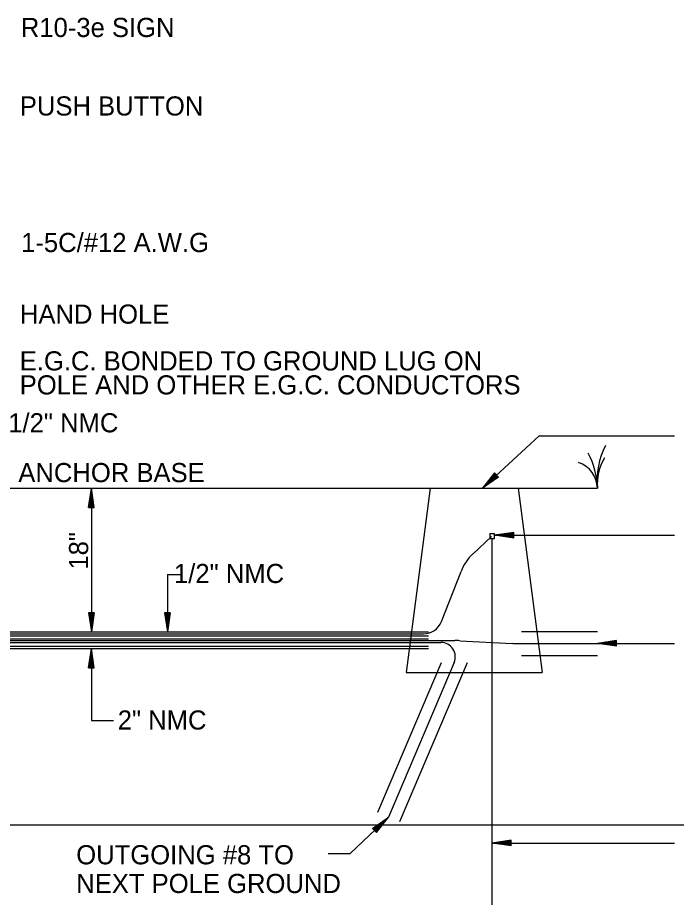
# Model space of a CAD drawing. Extents: x 418532 to 420296, y -565948 to -565286.
# Drawn here: x 418998.3 to 419153.1, y -565528 to -565321.2 of the extents above; entities that cross this region are included whole.
import ezdxf

# ---------------------------------------------------------------- set-up
doc = ezdxf.new("R2010")
doc.units = 0
doc.layers.add('R_Draft', color=7, linetype='Continuous')
doc.layers.add('Template', color=7, linetype='Continuous')

msp = doc.modelspace()

# ---------------------------------------------------------------- linework, layer by layer
at = {"layer": 'R_Draft'}
for p, q in [((419107.56, -565431.83), (419120.8, -565419.49)), ((419120.8, -565419.49), (419152.64, -565419.49)), ((419110.35, -565428.23), (419107.56, -565431.83)), ((419110.43, -565428.31), (419108.1, -565431.31)), ((419110.51, -565428.4), (419108.66, -565430.77)), ((419110.59, -565428.48), (419109.21, -565430.26)), ((419111.05, -565428.96), (419109.21, -565430.26)), ((419110.67, -565428.56), (419109.76, -565429.73)), ((419110.97, -565428.88), (419109.76, -565429.73)), ((419110.74, -565428.65), (419110.3, -565429.21)), ((419110.89, -565428.8), (419110.3, -565429.21)), ((419111.28, -565429.21), (419110.35, -565428.23)), ((419111.28, -565429.21), (419107.56, -565431.83)), ((419111.21, -565429.13), (419108.1, -565431.31)), ((419111.13, -565429.05), (419108.66, -565430.77)), ((418896.71, -565431.83), (419134.51, -565431.83)), ((419014.94, -565436.33), (419015.61, -565431.83)), ((419015.05, -565436.33), (419015.61, -565432.58)), ((419015.61, -565431.83), (419015.61, -565465.58)), ((419016.29, -565436.33), (419015.61, -565431.83)), ((419016.18, -565436.33), (419015.61, -565432.58)), ((419095.21, -565431.83), (419089.58, -565475.16)), ((419115.91, -565431.83), (419121.53, -565475.16)), ((419015.17, -565436.33), (419015.61, -565433.35)), ((419015.28, -565436.33), (419015.61, -565434.1)), ((419015.4, -565436.33), (419015.61, -565434.86)), ((419016.06, -565436.33), (419015.61, -565433.35)), ((419015.95, -565436.33), (419015.61, -565434.1)), ((419015.83, -565436.33), (419015.61, -565434.86)), ((419014.94, -565436.33), (419016.29, -565436.33)), ((419015.51, -565436.33), (419015.61, -565435.62)), ((419015.72, -565436.33), (419015.61, -565435.62)), ((419105.29, -565447.23), (419109.65, -565443.16)), ((419109.21, -565442.48), (419110.37, -565442.48)), ((419109.21, -565442.48), (419109.21, -565443.65)), ((419114.87, -565442.2), (419110.37, -565442.87)), ((419110.37, -565443.65), (419110.37, -565442.48)), ((419110.37, -565442.87), (419152.64, -565442.87)), ((419114.87, -565443.55), (419110.37, -565442.87)), ((419114.87, -565442.31), (419111.12, -565442.87)), ((419114.87, -565443.43), (419111.12, -565442.87)), ((419114.87, -565442.42), (419111.89, -565442.87)), ((419114.87, -565443.32), (419111.89, -565442.87)), ((419114.87, -565442.54), (419112.64, -565442.87)), ((419114.87, -565443.21), (419112.64, -565442.87)), ((419114.87, -565442.65), (419113.41, -565442.87)), ((419114.87, -565443.09), (419113.41, -565442.87)), ((419114.87, -565442.76), (419114.16, -565442.87)), ((419114.87, -565442.98), (419114.16, -565442.87)), ((419114.87, -565443.55), (419114.87, -565442.2)), ((419109.21, -565443.65), (419110.37, -565443.65)), ((419109.79, -565558.41), (419109.79, -565443.65)), ((419097.88, -565463.18), (419102.49, -565451.36)), ((419033.47, -565452.07), (419033.47, -565465.58)), ((419033.47, -565452.07), (419037.04, -565452.07)), ((419014.94, -565461.08), (419015.61, -565465.58)), ((419016.29, -565461.08), (419014.94, -565461.08)), ((419015.05, -565461.08), (419015.61, -565464.83)), ((419015.17, -565461.08), (419015.61, -565464.05)), ((419015.28, -565461.08), (419015.61, -565463.3)), ((419015.39, -565461.08), (419015.61, -565462.54)), ((419015.51, -565461.08), (419015.61, -565461.79)), ((419016.29, -565461.08), (419015.61, -565465.58)), ((419015.83, -565461.08), (419015.61, -565462.54)), ((419016.06, -565461.08), (419015.61, -565464.05)), ((419016.18, -565461.08), (419015.61, -565464.83)), ((419015.95, -565461.08), (419015.61, -565463.3)), ((419015.72, -565461.08), (419015.61, -565461.79)), ((419032.8, -565461.08), (419033.47, -565465.58)), ((419034.15, -565461.08), (419032.8, -565461.08)), ((419032.91, -565461.08), (419033.47, -565464.83)), ((419033.02, -565461.08), (419033.47, -565464.05)), ((419033.13, -565461.08), (419033.47, -565463.3)), ((419033.25, -565461.08), (419033.47, -565462.54)), ((419033.36, -565461.08), (419033.47, -565461.79)), ((419034.15, -565461.08), (419033.47, -565465.58)), ((419033.69, -565461.08), (419033.47, -565462.54)), ((419033.92, -565461.08), (419033.47, -565464.05)), ((419034.03, -565461.08), (419033.47, -565464.83)), ((419033.81, -565461.08), (419033.47, -565463.3)), ((419033.58, -565461.08), (419033.47, -565461.79)), ((418983.49, -565465.58), (419094.8, -565465.58)), ((418983.49, -565466.05), (419093.69, -565466.05)), ((419116.71, -565465.5), (419134.51, -565465.5)), ((418983.49, -565466.51), (419094.8, -565466.51)), ((418983.49, -565467.19), (419094.8, -565467.19)), ((418983.49, -565467.64), (419101.04, -565467.64)), ((418983.49, -565468.09), (419097.77, -565468.09)), ((419102.17, -565467.67), (419114.52, -565468.29)), ((419115.65, -565468.31), (419134.51, -565468.31)), ((419139.01, -565467.64), (419134.51, -565468.31)), ((419134.51, -565468.31), (419152.64, -565468.31)), ((419139.01, -565468.99), (419134.51, -565468.31)), ((419139.01, -565467.75), (419135.27, -565468.31)), ((419139.01, -565468.88), (419135.27, -565468.31)), ((419139.01, -565467.87), (419136.04, -565468.31)), ((419139.01, -565468.76), (419136.04, -565468.31)), ((419139.01, -565467.98), (419136.79, -565468.31)), ((419139.01, -565468.65), (419136.79, -565468.31)), ((419139.01, -565468.09), (419137.55, -565468.31)), ((419139.01, -565468.53), (419137.55, -565468.31)), ((419139.01, -565468.21), (419138.3, -565468.31)), ((419139.01, -565468.42), (419138.3, -565468.31)), ((419139.01, -565468.99), (419139.01, -565467.64)), ((418983.49, -565468.97), (419094.8, -565468.97)), ((418983.49, -565469.53), (419094.8, -565469.53)), ((419014.94, -565474.03), (419015.61, -565469.53)), ((419015.05, -565474.03), (419015.61, -565470.28)), ((419015.61, -565469.53), (419015.61, -565486.44)), ((419016.29, -565474.03), (419015.61, -565469.53)), ((419016.18, -565474.03), (419015.61, -565470.28)), ((419015.17, -565474.03), (419015.61, -565471.06)), ((419015.28, -565474.03), (419015.61, -565471.81)), ((419016.06, -565474.03), (419015.61, -565471.06)), ((419015.95, -565474.03), (419015.61, -565471.81)), ((419116.71, -565471.13), (419134.51, -565471.13)), ((419014.94, -565474.03), (419016.29, -565474.03)), ((419015.4, -565474.03), (419015.61, -565472.57)), ((419015.51, -565474.03), (419015.61, -565473.32)), ((419015.83, -565474.03), (419015.61, -565472.57)), ((419015.72, -565474.03), (419015.61, -565473.32)), ((419097.78, -565472.87), (419082.83, -565508.09)), ((419100.88, -565472.78), (419085.41, -565509.19)), ((419103.9, -565472.87), (419088, -565510.28)), ((419089.58, -565475.16), (419121.53, -565475.16)), ((419015.61, -565486.44), (419020.8, -565486.44)), ((419085.41, -565509.19), (419076.45, -565517.73)), ((419081.69, -565511.8), (419085.41, -565509.19)), ((419081.77, -565511.88), (419084.87, -565509.7)), ((419082.54, -565512.7), (419084.87, -565509.7)), ((419082.62, -565512.78), (419085.41, -565509.19)), ((419081.85, -565511.97), (419084.31, -565510.24)), ((419081.93, -565512.05), (419083.77, -565510.75)), ((419082.01, -565512.13), (419083.22, -565511.28)), ((419082.31, -565512.45), (419083.22, -565511.28)), ((419082.39, -565512.53), (419083.77, -565510.75)), ((419082.47, -565512.61), (419084.31, -565510.24)), ((419081.69, -565511.8), (419082.62, -565512.78)), ((419082.08, -565512.21), (419082.67, -565511.8)), ((419082.23, -565512.37), (419082.67, -565511.8)), ((419114.29, -565514.55), (419109.79, -565515.23)), ((419109.79, -565515.23), (419152.64, -565515.23)), ((419114.29, -565515.9), (419109.79, -565515.23)), ((419114.29, -565514.67), (419110.54, -565515.23)), ((419114.29, -565515.79), (419110.54, -565515.23)), ((419114.29, -565514.78), (419111.31, -565515.23)), ((419114.29, -565515.68), (419111.31, -565515.23)), ((419114.29, -565514.89), (419112.06, -565515.23)), ((419114.29, -565515.56), (419112.06, -565515.23)), ((419114.29, -565515.01), (419112.82, -565515.23)), ((419114.29, -565515.45), (419112.82, -565515.23)), ((419114.29, -565515.12), (419113.58, -565515.23)), ((419114.29, -565515.33), (419113.58, -565515.23)), ((419114.29, -565515.9), (419114.29, -565514.55)), ((419071.27, -565517.73), (419076.45, -565517.73))]:
    msp.add_line(p, q, dxfattribs=at)
for centre, radius, start, end in [((419153.39, -565430.17), 18.95, 153.6036, 185.017), ((419117.3, -565431.95), 17.21, 0.407, 29.2294), ((419146.46, -565430.85), 11.98, 149.1449, 184.6717), ((419128, -565431.94), 6.52, 1.0116, 71.214), ((419112.97, -565455.45), 11.25, 133.0617, 158.705), ((419093.69, -565461.55), 4.5, 270, 338.705), ((419097.77, -565471.46), 3.37, 336.984, 90), ((419101.04, -565490.14), 22.5, 87.1332, 90), ((419115.65, -565445.81), 22.5, 267.1332, 270)]:
    msp.add_arc(centre, radius, start, end, dxfattribs=at)
at = {"layer": 'Template'}
msp.add_lwpolyline([(419214.2, -565511.02), (418906.32, -565511.02), (418906.32, -565641.34), (419214.2, -565641.34)], close=True, dxfattribs=at)

# ---------------------------------------------------------------- texts
at = {"layer": 'R_Draft'}
for s, p in [('R10-3e SIGN', (418999.04, -565325.74)), ('PUSH BUTTON', (418998.8, -565344.2)), ('1-5C/#12 A.W.G', (418999.11, -565376.3)), ('HAND HOLE', (418998.83, -565393.13)), ('E.G.C. BONDED TO GROUND LUG ON ', (418998.78, -565404.13)), ('POLE AND OTHER E.G.C. CONDUCTORS', (418998.78, -565409.77)), (' 1/2" NMC ', (418994.42, -565418.68)), ('ANCHOR BASE', (418998.45, -565430.39)), (' 1/2" NMC ', (419033.36, -565454.11)), ('2" NMC', (419021.81, -565488.56)), ('OUTGOING #8 TO', (419012.06, -565520.24)), ('NEXT POLE GROUND', (419012.06, -565526.99))]:
    msp.add_text(s, height=4.5, dxfattribs=at).set_placement(p)
msp.add_text('18"', height=4.5, rotation=90, dxfattribs=at).set_placement((419014.86, -565450.95))

doc.saveas('drawing.dxf')
